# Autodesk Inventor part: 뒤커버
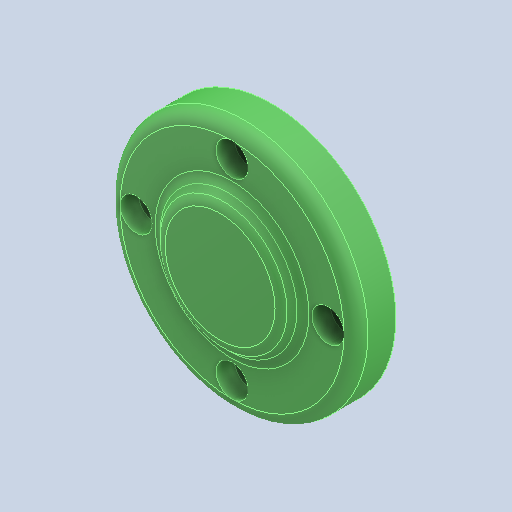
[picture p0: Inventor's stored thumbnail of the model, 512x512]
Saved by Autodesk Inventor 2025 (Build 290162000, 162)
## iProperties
Created: 2024-07
Part Number: 뒤커버
Material: 알루미늄 6061
Document SubType Name: Modeling
Designer: onair
Density: 2.71 g/cm^3
Appearance: 기본값
Author: jhkim
Sending System: Autodesk Inventor 2025
Preprocessor: ST-DEVELOPER v20
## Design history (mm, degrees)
feature "솔리드1"
node "솔리드2"
